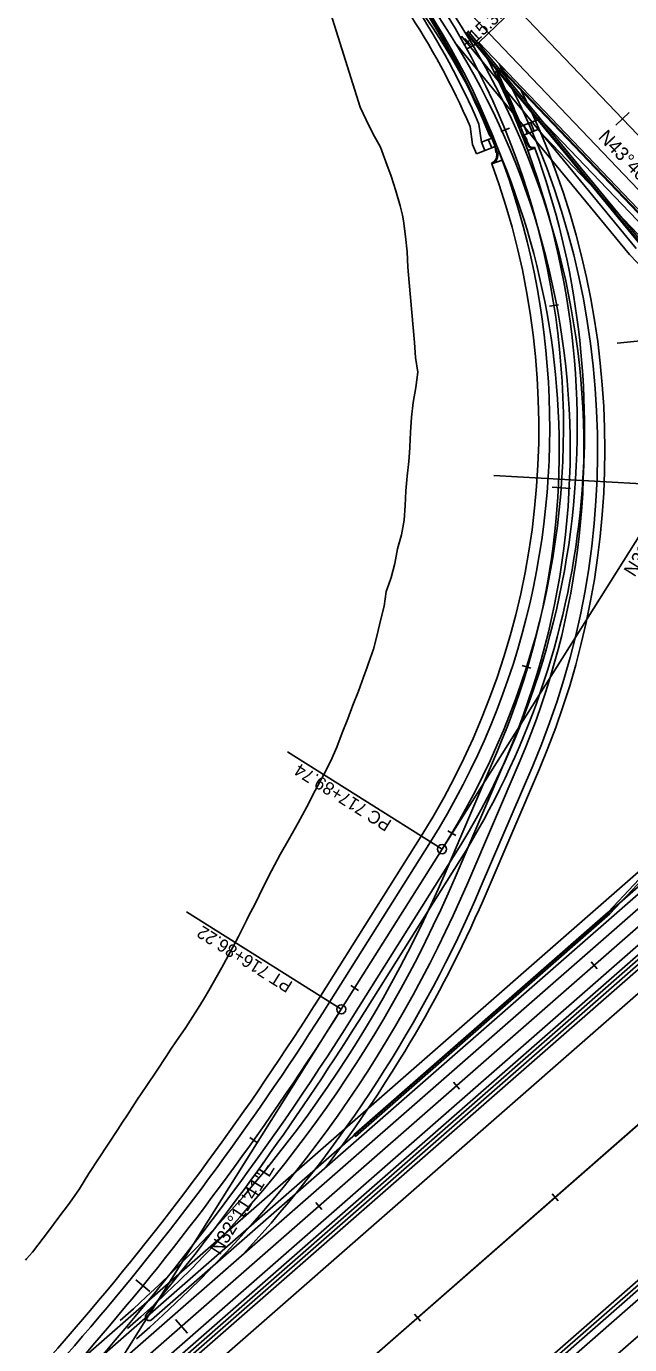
# Model space of a CAD drawing. Extents: x 1300404 to 1323571, y 237813 to 252077.
# Drawn here: x 1310171 to 1310501, y 240634 to 241355 of the extents above; entities that cross this region are included whole.
import ezdxf

# ---------------------------------------------------------------- set-up
doc = ezdxf.new("R2010")
doc.units = 0
for name, color, linetype in [('R_Barrier Wall', 7, 'Continuous'), ('R_Const Limits', 7, 'Continuous'), ('R_Curb', 7, 'Continuous'), ('R_Draft', 7, 'Continuous'), ('R_Future', 7, 'Continuous'), ('R_Horz Alg Annot', 7, 'Continuous'), ('R_Horz Alg Annot Leader', 7, 'Continuous'), ('R_Horz Alg Major Ticks', 7, 'Continuous'), ('R_Horz Alg Minor Ticks', 7, 'Continuous'), ('R_Horz Alg Tangents', 7, 'Continuous'), ('R_Horz Alg Tangents Text', 7, 'Continuous'), ('R_Lane Edge', 7, 'Continuous'), ('R_Proposed', 7, 'Continuous'), ('R_Shoulder', 7, 'Continuous'), ('R_Sidewalk Edge', 7, 'Continuous')]:
    doc.layers.add(name, color=color, linetype=linetype)

msp = doc.modelspace()

# ---------------------------------------------------------------- linework, layer by layer
at = {"layer": 'R_Barrier Wall'}
for p, q in [((1309593.62, 240046.84), (1310923.44, 241209.65)), ((1309594.94, 240045.34), (1310924.76, 241208.15)), ((1310489.06, 240870.1), (1310557.69, 240943.38)), ((1310490.03, 240869.19), (1310558.66, 240942.47)), ((1310349.89, 240748.42), (1310489.15, 240870.2)), ((1310350.76, 240747.42), (1310490.03, 240869.19)), ((1310349.89, 240748.42), (1310350.76, 240747.42))]:
    msp.add_line(p, q, dxfattribs=at)
at = {"layer": 'R_Const Limits'}
for points in [[(1310353.4, 241310.55), (1310353.4, 241310.55), (1310353.4, 241310.55), (1310353.4, 241310.55), (1310331.28, 241380.9), (1310331.28, 241380.9), (1310331.28, 241380.9), (1310331.28, 241380.9), (1310331.28, 241380.9), (1310331.28, 241380.9), (1310325.41, 241389.12), (1310320.8, 241395.02), (1310319.2, 241397.02), (1310312.88, 241404.81), (1310306.59, 241412.63), (1310300.69, 241420.82), (1310294.4, 241428.64), (1310288.08, 241436.43), (1310281.76, 241444.22), (1310274.87, 241451.47), (1310269.94, 241458.71)], [(1310170.16, 240679.83), (1310170.8, 240680.54), (1310174.03, 240684.11), (1310176.95, 240687.93), (1310179.86, 240691.77), (1310182.76, 240695.61), (1310188.54, 240703.3), (1310194.36, 240710.96), (1310199.82, 240718.89), (1310204.9, 240727.12), (1310210.13, 240735.21), (1310215.46, 240743.2), (1310220.69, 240751.26), (1310223.34, 240755.27), (1310225.99, 240759.27), (1310231.22, 240767.31), (1310236.58, 240775.25), (1310241.98, 240783.16), (1310247.23, 240791.17), (1310249.83, 240795.2), (1310252.45, 240799.2), (1310257.89, 240807.07), (1310263.08, 240815.12), (1310265.65, 240819.15), (1310268.15, 240823.23), (1310270.55, 240827.38), (1310272.93, 240831.54), (1310277.65, 240839.87), (1310282.29, 240848.25), (1310286.78, 240856.91), (1310291.29, 240865.89), (1310292.37, 240867.97), (1310295.91, 240874.8), (1310300.28, 240883.86), (1310304.87, 240892.79), (1310309.55, 240901.66), (1310314.55, 240910.33), (1310319.44, 240919.07), (1310324.23, 240927.87), (1310328.81, 240936.8), (1310333.58, 240945.56), (1310337.37, 240952.89), (1310340.64, 240960.48), (1310343.57, 240968.2), (1310346.57, 240975.84), (1310349.45, 240983.49), (1310352.42, 240991.06), (1310355.31, 240998.65), (1310357.3, 241004.12), (1310358.05, 241006.29), (1310360.63, 241013.97), (1310362.67, 241021.83), (1310364.6, 241029.69), (1310366.48, 241037.54), (1310367.68, 241045.55), (1310369.04, 241049.57), (1310370.3, 241053.17), (1310372.29, 241060.97), (1310373.78, 241068.88), (1310376.03, 241076.65), (1310377.56, 241084.58), (1310377.98, 241092.66), (1310378.46, 241100.7), (1310379.2, 241108.71), (1310379.95, 241116.73), (1310380.61, 241124.27), (1310380.62, 241124.77), (1310381.04, 241132.82), (1310381.55, 241140.9), (1310382.39, 241149.01), (1310383.82, 241157.22), (1310384.89, 241165.49), (1310383.76, 241173.6), (1310383.19, 241181.77), (1310382.47, 241189.95), (1310381.71, 241198.14), (1310381, 241206.38), (1310380.23, 241214.64), (1310379.51, 241222.98), (1310379.11, 241231.46), (1310378.2, 241239.88), (1310377.07, 241248.31), (1310376.63, 241251.47), (1310375.36, 241256.61), (1310373, 241264.72), (1310370.44, 241272.78), (1310367.52, 241280.71), (1310364.45, 241288.61), (1310360.42, 241296.06), (1310356.65, 241303.63), (1310353.4, 241310.55), (1310353.4, 241310.55), (1310353.4, 241310.55)]]:
    msp.add_lwpolyline(points, dxfattribs=at)
at = {"layer": 'R_Curb'}
for p, q in [((1310431.61, 241329.88), (1310671.61, 241078.44)), ((1310431.97, 241330.23), (1310671.99, 241078.77)), ((1310440.91, 241301.94), (1310441.2, 241299.9)), ((1310425.4, 241293.63), (1310424.18, 241295.3)), ((1310444.23, 241293.57), (1310443.04, 241295.25)), ((1310427.24, 241288.98), (1310427.5, 241286.93)), ((1310448.76, 241288.6), (1310448.94, 241288.13)), ((1310425.28, 241279.97), (1310425.45, 241279.5))]:
    msp.add_line(p, q, dxfattribs=at)
for centre, radius, start, end in [((1310032.27, 241135.01), 423.42, 22.2443, 43.66667), ((1310032.27, 241135.01), 423.92, 21.97246, 43.66667), ((1310430.52, 241328.85), 2, 43.66667, 205.95345), ((1310032.27, 241135.01), 440.92, 21.96023, 25.95273), ((1310430.52, 241328.85), 1.5, 43.66667, 205.95345), ((1310032.27, 241135.01), 441.42, 22.21947, 25.95273), ((1310032.27, 241135.01), 440.92, 20.56508, 21.3105), ((1310032.27, 241135.01), 441.42, 20.56508, 21.05126), ((1310423.73, 241284.19), 4.5, 290.17787, 20.86173), ((1310423.73, 241284.19), 5, 290.17787, 20.86173), ((1310032.27, 241135.01), 423.92, 20.86173, 21.29747), ((1310032.27, 241135.01), 423.42, 20.86173, 21.02643), ((1310447.9, 241290.95), 3, 200.56423, 290.17787), ((1310447.9, 241290.95), 2.5, 200.56423, 290.17787)]:
    msp.add_arc(centre, radius, start, end, dxfattribs=at)
at = {"layer": 'R_Draft'}
msp.add_line((1310418.29, 241346.01), (1310411.71, 241342.42), dxfattribs=at)
at = {"layer": 'R_Future'}
for p, q in [((1311714.76, 241726.24), (1309950.43, 240183.5)), ((1311716.07, 241724.73), (1309951.75, 240181.99)), ((1311717.39, 241723.23), (1309953.06, 240180.49)), ((1311720.02, 241720.22), (1309955.69, 240177.48)), ((1310504.53, 241233.21), (1310408.91, 241349.31)), ((1310506.77, 241235.21), (1310411.16, 241351.31)), ((1310411.52, 241351.65), (1310507.13, 241235.55)), ((1310412.25, 241352.34), (1310507.86, 241236.24)), ((1310500.78, 241229.89), (1310405.17, 241345.99)), ((1310500.78, 241229.89), (1310643.48, 241080.39)), ((1310426.48, 241108.99), (1310520.85, 241103.66)), ((1309569.9, 240073.92), (1310598.82, 240973.62)), ((1309573.85, 240069.41), (1310602.77, 240969.1)), ((1310399.86, 240891.49), (1310428.53, 240958.46)), ((1310405.37, 240889.13), (1310434.04, 240956.1)), ((1310412.27, 240886.18), (1310440.94, 240953.15)), ((1310419.16, 240883.23), (1310447.83, 240950.19)), ((1310422.84, 240881.65), (1310451.51, 240948.62)), ((1310616.69, 240735.53), (1309965.57, 240166.18))]:
    msp.add_line(p, q, dxfattribs=at)
for centre, radius, start, end in [((1310043.42, 241123.33), 432.42, 336.82333, 43.66667), ((1310043.42, 241123.33), 424.92, 336.82333, 43.66667), ((1310043.42, 241123.33), 418.92, 336.82333, 36.25513), ((1310043.42, 241123.33), 439.92, 336.82333, 28.66161), ((1310043.42, 241123.33), 443.92, 336.82333, 26.18643), ((1309773.83, 241159.51), 680.99, 311.16667, 336.82333), ((1309773.83, 241159.51), 686.99, 311.16667, 336.82333), ((1309773.83, 241159.51), 694.49, 311.16667, 336.82333), ((1309773.83, 241159.51), 701.99, 317.28606, 336.82333), ((1309773.83, 241159.51), 705.99, 322.59605, 336.82333)]:
    msp.add_arc(centre, radius, start, end, dxfattribs=at)
at = {"layer": 'R_Horz Alg Annot Leader'}
msp.add_line((1310418.29, 241346.01), (1310432.36, 241359.45), dxfattribs=at)
for points in [[(1310494.1, 241181.4), (1310577.76, 241189.8)], [(1310398.2, 240904.62), (1310313.58, 240957.9)], [(1310343.05, 240817.02), (1310258.43, 240870.3)]]:
    msp.add_lwpolyline(points, dxfattribs=at)
at = {"layer": 'R_Horz Alg Major Ticks'}
for points in [[(1310500.63, 241307.54), (1310493.4, 241300.63)], [(1310458.47, 241102.71), (1310468.44, 241101.95)], [(1310230.61, 240669.02), (1310238.36, 240662.7)], [(1310252.28, 240647.36), (1310258.87, 240639.83)]]:
    msp.add_lwpolyline(points, dxfattribs=at)
at = {"layer": 'R_Horz Alg Minor Ticks'}
for points in [[(1310430.42, 241297.21), (1310435.05, 241299.1)], [(1310457, 241201.64), (1310461.94, 241202.41)], [(1310442.1, 241005.13), (1310446.87, 241003.61)], [(1310401.42, 240914.65), (1310405.72, 240912.09)], [(1310479.77, 240842.95), (1310483.06, 240839.19)], [(1310348.28, 240830.01), (1310352.51, 240827.35)], [(1310404.49, 240777.12), (1310407.78, 240773.36)], [(1310293.04, 240746.84), (1310297.12, 240743.94)], [(1310458.48, 240716.07), (1310461.77, 240712.31)], [(1310329.21, 240711.3), (1310332.5, 240707.54)], [(1310383.2, 240650.25), (1310386.49, 240646.48)]]:
    msp.add_lwpolyline(points, dxfattribs=at)
at = {"layer": 'R_Horz Alg Tangents'}
for p, q in [((1310577.76, 241189.8), (1310345.07, 241433.58)), ((1310398.2, 240904.62), (1310577.76, 241189.8)), ((1310224.01, 240627.95), (1310343.05, 240817.02))]:
    msp.add_line(p, q, dxfattribs=at)
at = {"layer": 'R_Lane Edge'}
for p, q in [((1310418.29, 241346.01), (1311200.16, 240526.88)), ((1310448.95, 241288.13), (1310445.19, 241286.76)), ((1309254.07, 239731.34), (1311026.82, 241281.45)), ((1310431.11, 241281.58), (1310425.45, 241279.5)), ((1310188.6, 240594.99), (1310884.73, 241203.69)), ((1309589.65, 240051.34), (1310894.61, 241192.4)), ((1310336.7, 240821.01), (1310391.86, 240908.61)), ((1310349.4, 240813.02), (1310404.55, 240900.62))]:
    msp.add_line(p, q, dxfattribs=at)
for centre, radius, start, end in [((1310032.27, 241135.01), 424.92, 327.80537, 43.66667), ((1310032.27, 241135.01), 439.92, 327.80537, 28.66161), ((1310430.52, 241328.85), 3, 43.66667, 205.95323), ((1309050.08, 241631.07), 1520.39, 311.16667, 327.80537), ((1309050.08, 241631.07), 1535.39, 317.70521, 327.80537)]:
    msp.add_arc(centre, radius, start, end, dxfattribs=at)
at = {"layer": 'R_Proposed'}
for p, q in [((1308427.57, 238936.91), (1312793.8, 242754.77)), ((1309180.37, 239595.16), (1312398.96, 242409.52)), ((1310151.78, 241665.77), (1311952.58, 239779.15)), ((1310165.59, 241651.3), (1311952.63, 239779.09)), ((1310165.59, 241651.3), (1311952.63, 239779.09)), ((1309584.71, 240056.98), (1310889.67, 241198.05)), ((1310343.05, 240817.02), (1310398.2, 240904.62)), ((1310343.05, 240817.02), (1310398.2, 240904.62))]:
    msp.add_line(p, q, dxfattribs=at)
for centre in [(1310398.2, 240904.62), (1310343.05, 240817.02)]:
    msp.add_circle(centre, 2.5, dxfattribs=at)
for centre, radius, start, end in [((1310032.27, 241135.01), 432.42, 327.80537, 43.66667), ((1310032.27, 241135.01), 432.42, 327.80537, 43.66667), ((1309050.08, 241631.07), 1527.89, 311.16667, 327.80537), ((1309050.08, 241631.07), 1527.89, 311.16667, 327.80537)]:
    msp.add_arc(centre, radius, start, end, dxfattribs=at)
at = {"layer": 'R_Shoulder'}
for p, q in [((1309482.39, 239944.26), (1311020.24, 241288.97)), ((1310239.17, 240647.18), (1310880.78, 241208.21)), ((1309592.28, 240048.33), (1310897.24, 241189.39)), ((1310331.63, 240824.21), (1310386.78, 240911.81)), ((1310352.78, 240810.89), (1310407.94, 240898.49))]:
    msp.add_line(p, q, dxfattribs=at)
for centre, radius, start, end in [((1310032.27, 241135.01), 443.92, 327.80537, 20.17787), ((1310032.27, 241135.01), 418.92, 327.80537, 20.17787), ((1309050.08, 241631.07), 1514.39, 311.16667, 327.80537), ((1309050.08, 241631.07), 1539.39, 320.40656, 327.80537), ((1310237.86, 240648.69), 2, 140.40656, 311.16667)]:
    msp.add_arc(centre, radius, start, end, dxfattribs=at)
at = {"layer": 'R_Sidewalk Edge'}
for p, q in [((1310413.57, 241299.89), (1310414.95, 241290.13)), ((1310418.43, 241301.25), (1310419.82, 241291.42)), ((1310440.27, 241299.53), (1310451.99, 241304.18)), ((1310442.11, 241294.88), (1310450.7, 241298.29)), ((1310450.7, 241298.29), (1310653.59, 241085.74)), ((1310451.99, 241304.18), (1310653.75, 241092.8)), ((1310419.82, 241291.42), (1310426.33, 241294)), ((1310419.82, 241291.42), (1310421.66, 241286.77)), ((1310423.54, 241292.89), (1310425.38, 241288.25)), ((1310425.4, 241293.63), (1310427.24, 241288.98)), ((1310414.95, 241290.13), (1310417.02, 241284.93)), ((1310417.02, 241284.93), (1310428.17, 241289.35))]:
    msp.add_line(p, q, dxfattribs=at)
for radius, start, end in [(415.42, 23.38359, 43.66667), (420.42, 23.29162, 43.66667), (440.92, 21.31486, 21.95587), (442.92, 21.31486, 21.95587), (446.92, 21.31486, 21.95587)]:
    msp.add_arc((1310032.27, 241135.01), radius, start, end, dxfattribs=at)

# ---------------------------------------------------------------- texts
at = {"layer": 'R_Horz Alg Annot'}
for s, rotation, p in [('+15.31', 43.07689, (1310412.7, 241341.99)), ('PC 717+89.74', 147.80537, (1310371.18, 240919.86)), ('PT 716+86.22', 147.80537, (1310317.02, 240831.63))]:
    msp.add_text(s, height=7, rotation=rotation, dxfattribs=at).set_placement(p)
at = {"layer": 'R_Horz Alg Tangents Text'}
for s, rotation, p in [('N43%%d40\'00"W', 313.66667, (1310483.27, 241293.8)), ('N32%%d11\'41"E', 57.80537, (1310503.58, 241053.07)), ('N32%%d11\'41"E', 57.80537, (1310276.62, 240682.17))]:
    msp.add_text(s, height=7.5, rotation=rotation, dxfattribs=at).set_placement(p)

doc.saveas('drawing.dxf')
